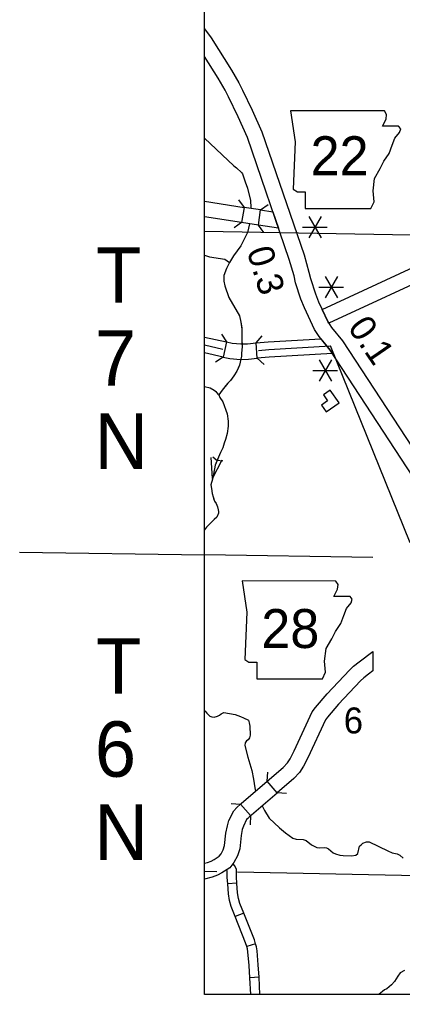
# Model space of a CAD drawing. Extents: x 1374139 to 1377472, y 1168351 to 1170484.
# Drawn here: x 1375030 to 1375154.2, y 1168653.8 to 1168970.5 of the extents above; entities that cross this region are included whole.
import ezdxf

# ---------------------------------------------------------------- set-up
doc = ezdxf.new("R2010")
doc.units = 0
for name, color, linetype in [('14', 7, 'Continuous'), ('26', 7, 'Continuous'), ('Default', 7, 'Continuous')]:
    doc.layers.add(name, color=color, linetype=linetype)

msp = doc.modelspace()

# ---------------------------------------------------------------- linework, layer by layer
at = {"layer": '14'}
msp.add_line((1375030.01, 1168797.49), (1375090, 1168796.6), dxfattribs=at)
at = {"layer": '26'}
msp.add_lwpolyline([(1375090, 1169579.43), (1376597.43, 1169579.43), (1376597.43, 1168653.79), (1375090, 1168653.79)], close=True, dxfattribs=at)
at = {"layer": 'Default'}
for p, q in [((1375090, 1168958.55), (1375090, 1168967.47)), ((1375090, 1168967.47), (1375092.12, 1168964.57)), ((1375092.12, 1168964.57), (1375098.76, 1168954.03)), ((1375094.49, 1168951.44), (1375090, 1168958.55)), ((1375098.76, 1168954.03), (1375101.14, 1168949.96)), ((1375096.74, 1168947.58), (1375094.49, 1168951.44)), ((1375101.14, 1168949.96), (1375102.31, 1168947.59)), ((1375097.81, 1168945.41), (1375096.74, 1168947.58)), ((1375102.31, 1168947.59), (1375105.45, 1168941.02)), ((1375100.91, 1168938.92), (1375097.81, 1168945.41)), ((1375105.45, 1168941.02), (1375108.6, 1168933.98)), ((1375103.94, 1168932.14), (1375100.91, 1168938.92)), ((1375108.6, 1168933.98), (1375122.29, 1168894.07)), ((1375117.52, 1168892.58), (1375103.94, 1168932.14)), ((1375090, 1168906.41), (1375090, 1168911.46)), ((1375090, 1168911.46), (1375102.84, 1168909.49)), ((1375102.84, 1168909.49), (1375102.03, 1168904.56)), ((1375107.48, 1168903.72), (1375108.21, 1168908.67)), ((1375102.03, 1168904.56), (1375090, 1168906.41)), ((1375112.21, 1168908.06), (1375114.04, 1168902.72)), ((1375127.82, 1168906.54), (1375123.82, 1168899.61)), ((1375123.82, 1168906.54), (1375127.82, 1168899.61)), ((1375121.82, 1168903.07), (1375129.82, 1168903.07)), ((1375122.29, 1168894.07), (1375123.89, 1168888.44)), ((1375119.04, 1168887.2), (1375117.52, 1168892.58)), ((1375119.55, 1168885), (1375119.04, 1168887.2)), ((1375123.89, 1168888.44), (1375124.37, 1168886.33)), ((1375133.12, 1168887), (1375129.12, 1168880.07)), ((1375129.12, 1168887), (1375133.12, 1168880.07)), ((1375121.27, 1168879.68), (1375119.55, 1168885)), ((1375124.37, 1168886.33), (1375125.96, 1168881.41)), ((1375127.12, 1168883.54), (1375135.12, 1168883.54)), ((1375125.96, 1168881.41), (1375127.03, 1168878.85)), ((1375122.44, 1168876.85), (1375121.27, 1168879.68)), ((1375127.03, 1168878.85), (1375130.07, 1168872.21)), ((1375125.69, 1168869.78), (1375122.44, 1168876.85)), ((1375130.07, 1168872.21), (1375131.19, 1168870.5)), ((1375127.15, 1168867.54), (1375125.69, 1168869.78)), ((1375130.76, 1168863.14), (1375127.15, 1168867.54)), ((1375131.19, 1168870.5), (1375134.8, 1168866.1)), ((1375090, 1168862.23), (1375090, 1168867.35)), ((1375090, 1168867.35), (1375097.14, 1168865.77)), ((1375097.14, 1168865.77), (1375096.09, 1168860.88)), ((1375107.08, 1168860.46), (1375106.73, 1168865.45)), ((1375134.8, 1168866.1), (1375177.57, 1168800.51)), ((1375096.09, 1168860.88), (1375090, 1168862.23)), ((1375171.6, 1168800.51), (1375130.76, 1168863.14)), ((1375131.17, 1168859.93), (1375127.17, 1168853)), ((1375127.17, 1168859.93), (1375131.17, 1168853)), ((1375125.17, 1168856.47), (1375133.17, 1168856.47)), ((1375092.59, 1168821.36), (1375092.22, 1168828.21)), ((1375092.59, 1168821.36), (1375095.7, 1168827.48)), ((1375092.69, 1168828.41), (1375094.14, 1168827.3)), ((1375095.97, 1168827.06), (1375094.16, 1168827.29)), ((1375140.13, 1168761.84), (1375144.64, 1168765.16)), ((1375144.64, 1168765.16), (1375144.64, 1168758.95)), ((1375137.05, 1168759.17), (1375138.38, 1168760.41)), ((1375138.38, 1168760.41), (1375140.13, 1168761.84)), ((1375129.79, 1168751.42), (1375137.05, 1168759.17)), ((1375141.68, 1168756.65), (1375140.59, 1168755.63)), ((1375143.19, 1168757.89), (1375141.68, 1168756.65)), ((1375144.64, 1168758.95), (1375143.19, 1168757.89)), ((1375140.59, 1168755.63), (1375133.5, 1168748.07)), ((1375125.99, 1168747.04), (1375129.79, 1168751.42)), ((1375124.91, 1168745.57), (1375125.99, 1168747.04)), ((1375133.5, 1168748.07), (1375129.9, 1168743.92)), ((1375119.06, 1168732.9), (1375124.91, 1168745.57)), ((1375129.9, 1168743.92), (1375129.24, 1168743.02)), ((1375129.24, 1168743.02), (1375123.56, 1168730.72)), ((1375117.8, 1168730.39), (1375119.06, 1168732.9)), ((1375115.57, 1168727.58), (1375116.91, 1168729)), ((1375116.91, 1168729), (1375117.8, 1168730.39)), ((1375123.56, 1168730.72), (1375122.15, 1168727.92)), ((1375110.31, 1168723.07), (1375115.57, 1168727.58)), ((1375120.87, 1168725.92), (1375119.03, 1168723.96)), ((1375122.15, 1168727.92), (1375120.87, 1168725.92)), ((1375113.61, 1168719.31), (1375110.31, 1168723.07)), ((1375119.03, 1168723.96), (1375113.61, 1168719.31)), ((1375100.45, 1168714.51), (1375101.66, 1168715.63)), ((1375101.66, 1168715.63), (1375104.98, 1168711.89)), ((1375097.95, 1168710.35), (1375099.47, 1168713.4)), ((1375099.47, 1168713.4), (1375100.45, 1168714.51)), ((1375097.43, 1168708.63), (1375097.95, 1168710.35)), ((1375103.66, 1168710.59), (1375102.62, 1168708.49)), ((1375104.03, 1168711.01), (1375103.66, 1168710.59)), ((1375104.98, 1168711.89), (1375104.03, 1168711.01)), ((1375096.54, 1168702.15), (1375096.92, 1168706.21)), ((1375096.92, 1168706.21), (1375097.43, 1168708.63)), ((1375102.28, 1168707.39), (1375101.88, 1168705.46)), ((1375102.62, 1168708.49), (1375102.28, 1168707.39)), ((1375101.88, 1168705.46), (1375101.47, 1168701.12)), ((1375095.37, 1168699.46), (1375096.09, 1168700.78)), ((1375096.09, 1168700.78), (1375096.54, 1168702.15)), ((1375101.47, 1168701.12), (1375100.7, 1168698.79)), ((1375090, 1168696.41), (1375091, 1168696.65)), ((1375090, 1168691.28), (1375090, 1168696.41)), ((1375091, 1168696.65), (1375092.14, 1168697.08)), ((1375092.14, 1168697.08), (1375093.11, 1168697.6)), ((1375093.11, 1168697.6), (1375094.77, 1168698.69)), ((1375094.77, 1168698.69), (1375095.37, 1168699.46)), ((1375099.56, 1168696.69), (1375098.19, 1168694.96)), ((1375100.7, 1168698.79), (1375099.56, 1168696.69)), ((1375095.68, 1168693.3), (1375094.22, 1168692.52)), ((1375098.19, 1168694.96), (1375095.68, 1168693.3)), ((1375092.46, 1168691.85), (1375090, 1168691.28)), ((1375094.22, 1168692.52), (1375092.46, 1168691.85)), ((1375100.54, 1168689.99), (1375097.55, 1168689.79)), ((1375102.75, 1168680.22), (1375099.96, 1168679.11)), ((1375106.59, 1168670.24), (1375103.71, 1168669.39)), ((1375107.69, 1168659.42), (1375104.69, 1168659.25))]:
    msp.add_line(p, q, dxfattribs=at)
for points in [[(1375117.94, 1168940.9), (1375119.46, 1168930.75), (1375118.78, 1168915.35), (1375120.14, 1168914.51), (1375122.68, 1168914.51), (1375122.68, 1168909.09), (1375143.99, 1168909.09), (1375145.01, 1168911.29), (1375144.67, 1168914.84), (1375145.18, 1168918.9), (1375147.04, 1168922.12), (1375148.22, 1168924.49), (1375149.91, 1168927.03), (1375150.93, 1168929.73), (1375151.77, 1168931.93), (1375153.3, 1168933.79), (1375153.64, 1168934.98), (1375152.96, 1168935.82), (1375147.71, 1168935.82), (1375148.9, 1168938.19), (1375149.07, 1168939.71), (1375148.37, 1168940.88)], [(1375133.67, 1168845.97), (1375130.76, 1168850.14), (1375128.56, 1168848.6), (1375129.94, 1168846.63), (1375127.97, 1168845.26), (1375129.5, 1168843.06)], [(1375102.23, 1168788.13), (1375103.75, 1168777.98), (1375103.07, 1168762.58), (1375104.42, 1168761.74), (1375106.96, 1168761.74), (1375106.96, 1168756.32), (1375128.28, 1168756.32), (1375129.29, 1168758.52), (1375128.96, 1168762.08), (1375129.46, 1168766.14), (1375131.32, 1168769.35), (1375132.51, 1168771.72), (1375134.2, 1168774.26), (1375135.22, 1168776.96), (1375136.06, 1168779.16), (1375137.58, 1168781.02), (1375137.92, 1168782.21), (1375137.25, 1168783.05), (1375132, 1168783.05), (1375133.19, 1168785.42), (1375133.35, 1168786.95), (1375132.65, 1168788.11)]]:
    msp.add_lwpolyline(points, close=True, dxfattribs=at)
for points in [[(1375090, 1168931.98), (1375099.51, 1168922.99), (1375100.34, 1168922.38), (1375102.01, 1168920.85), (1375102.31, 1168920.39), (1375103.21, 1168917.81)], [(1375103.21, 1168917.81), (1375103.92, 1168915.71), (1375104.91, 1168911.67), (1375105.07, 1168909.41), (1375105.07, 1168909.2)], [(1375101.08, 1168911.93), (1375102.84, 1168909.49)], [(1375108.21, 1168908.67), (1375102.84, 1168909.49)], [(1375108.21, 1168908.67), (1375110.61, 1168910.46)], [(1375108.21, 1168908.67), (1375112.21, 1168908.06)], [(1375104.6, 1168904.13), (1375103.97, 1168901.32), (1375101.76, 1168897.04), (1375099.37, 1168893.76), (1375098.17, 1168891.63), (1375097.16, 1168889.65), (1375096.26, 1168887.34), (1375096.29, 1168885.54), (1375096.6, 1168884.04), (1375097.93, 1168880.2), (1375101.33, 1168874.28)], [(1375102.03, 1168904.56), (1375099.59, 1168902.81)], [(1375107.48, 1168903.72), (1375102.03, 1168904.56)], [(1375109.27, 1168901.32), (1375107.48, 1168903.72)], [(1375114.04, 1168902.72), (1375107.48, 1168903.72)], [(1375193.67, 1168899.77), (1375090, 1168901.68)], [(1375090, 1168893.91), (1375091.6, 1168893.38), (1375096.64, 1168892.64), (1375098.17, 1168891.63)], [(1375128.18, 1168876.34), (1375166.71, 1168894.16)], [(1375168.77, 1168889.6), (1375130.32, 1168871.83)], [(1375101.33, 1168874.28), (1375101.82, 1168872.15), (1375102.16, 1168869.89), (1375102.09, 1168868.17), (1375102.13, 1168865.99), (1375102.22, 1168864.32), (1375101.98, 1168862), (1375101.99, 1168861.2), (1375101.41, 1168858.25), (1375100.52, 1168856.24), (1375099.54, 1168854.73), (1375098.45, 1168853.3), (1375097.6, 1168852.41), (1375095.69, 1168850.13), (1375094.61, 1168848.64), (1375095.03, 1168847.68), (1375095.94, 1168846.28), (1375097.33, 1168842.45), (1375097.67, 1168839.99), (1375097.66, 1168838.46), (1375097.4, 1168836.08), (1375096.77, 1168834.07), (1375096.4, 1168832.94), (1375095.93, 1168831.4), (1375095.24, 1168829.91), (1375094.91, 1168829.15), (1375093.52, 1168825.75), (1375092.9, 1168822.82), (1375092.61, 1168821.19), (1375092.05, 1168819.37), (1375092.29, 1168818.15), (1375092.47, 1168816.58), (1375092.79, 1168815.46), (1375093.26, 1168814.05), (1375093.75, 1168813.25), (1375094.2, 1168812.17), (1375094.53, 1168810.71), (1375094.53, 1168810.17), (1375094.02, 1168808.9), (1375093.15, 1168808.05), (1375091.84, 1168806.76), (1375090.69, 1168805.65), (1375090.02, 1168804.77), (1375090, 1168804.73)], [(1375101.33, 1168874.28), (1375101.82, 1168872.15), (1375102.09, 1168870.39)], [(1375130.32, 1168871.83), (1375130.07, 1168872.21), (1375128.18, 1168876.34)], [(1375095.52, 1168868.29), (1375097.14, 1168865.77)], [(1375102.1, 1168867.76), (1375102.13, 1168865.99), (1375102.18, 1168865.17)], [(1375106.73, 1168865.45), (1375108.7, 1168867.71)], [(1375090, 1168864.79), (1375095.98, 1168863.47)], [(1375097.14, 1168865.77), (1375099.03, 1168865.35), (1375101.8, 1168865.12), (1375103.92, 1168865.21), (1375106.73, 1168865.45)], [(1375106.73, 1168865.45), (1375110.66, 1168865.78), (1375127.75, 1168866.82)], [(1375107.5, 1168863), (1375110.84, 1168863.28), (1375130.93, 1168864.51)], [(1375127.75, 1168866.82), (1375130.76, 1168863.14), (1375131.48, 1168862.04)], [(1375156.67, 1168800.51), (1375130.93, 1168864.51)], [(1375131.48, 1168862.04), (1375111.02, 1168860.79), (1375107.08, 1168860.46)], [(1375096.09, 1168860.88), (1375093.57, 1168859.25)], [(1375096.09, 1168860.88), (1375098.28, 1168860.4), (1375101.69, 1168860.11), (1375104.23, 1168860.22), (1375107.08, 1168860.46)], [(1375109.35, 1168858.49), (1375107.08, 1168860.46)], [(1375101.01, 1168857.35), (1375100.52, 1168856.24), (1375099.54, 1168854.73), (1375098.45, 1168853.3), (1375097.6, 1168852.41), (1375096.4, 1168850.97)], [(1375094.61, 1168848.64), (1375093.88, 1168849.48), (1375093.18, 1168849.99), (1375091.86, 1168850.74), (1375090, 1168851.15)], [(1375094.79, 1168848.89), (1375094.61, 1168848.64), (1375095.03, 1168847.68), (1375095.94, 1168846.28), (1375097.33, 1168842.45), (1375097.44, 1168841.63)], [(1375097.66, 1168839.01), (1375097.66, 1168838.46), (1375097.4, 1168836.08), (1375096.77, 1168834.07), (1375096.4, 1168832.94), (1375095.93, 1168831.4), (1375095.9, 1168831.33)], [(1375094.82, 1168828.93), (1375093.52, 1168825.75), (1375092.9, 1168822.82), (1375092.64, 1168821.35)], [(1375092.16, 1168818.81), (1375092.29, 1168818.15), (1375092.47, 1168816.58), (1375092.79, 1168815.46), (1375092.96, 1168814.95)], [(1375092.96, 1168814.95), (1375093.26, 1168814.05), (1375093.75, 1168813.25), (1375094.2, 1168812.17), (1375094.4, 1168811.28)], [(1375093.92, 1168808.8), (1375093.15, 1168808.05), (1375091.84, 1168806.76), (1375090.69, 1168805.65), (1375090.02, 1168804.77), (1375090, 1168804.73)], [(1375144.64, 1168795.79), (1375090, 1168796.6)], [(1375090, 1168746.09), (1375090.23, 1168745.78), (1375090.73, 1168745.2), (1375091.42, 1168744.5), (1375091.76, 1168744.24), (1375092.38, 1168743.95), (1375093.1, 1168743.83), (1375094.22, 1168744.2), (1375094.89, 1168744.57), (1375095.39, 1168744.95), (1375096.27, 1168745.36), (1375098.16, 1168745.11), (1375099.95, 1168744.72), (1375101.69, 1168744.11), (1375102.65, 1168743.64)], [(1375090, 1168746.09), (1375090.23, 1168745.78), (1375090.73, 1168745.2), (1375091.42, 1168744.5), (1375091.76, 1168744.24), (1375092.38, 1168743.95), (1375093.1, 1168743.83), (1375093.91, 1168744.1)], [(1375096.23, 1168745.34), (1375096.27, 1168745.36), (1375098.16, 1168745.11), (1375099.95, 1168744.72), (1375101.69, 1168744.11), (1375102.65, 1168743.64)], [(1375102.65, 1168743.64), (1375104.23, 1168742.87), (1375104.52, 1168742.07), (1375104.75, 1168740.97), (1375104.81, 1168738), (1375104.61, 1168737.22), (1375104.16, 1168736.54), (1375103.66, 1168736.17), (1375103.25, 1168735.55), (1375103.08, 1168734.69), (1375104.06, 1168730.89), (1375105.39, 1168726.53), (1375105.91, 1168723.79), (1375106.33, 1168720.88), (1375106.59, 1168719.89)], [(1375110.31, 1168723.07), (1375110.51, 1168726.06)], [(1375101.66, 1168715.63), (1375101.88, 1168715.84), (1375110.31, 1168723.07)], [(1375104.98, 1168711.89), (1375105.21, 1168712.1), (1375113.61, 1168719.31)], [(1375116.6, 1168719.11), (1375113.61, 1168719.31)], [(1375098.66, 1168715.8), (1375101.66, 1168715.63)], [(1375108.69, 1168715.03), (1375109.46, 1168713.55), (1375111, 1168711.1), (1375114.38, 1168707.9), (1375116.23, 1168706.31), (1375118.66, 1168704.6), (1375119.7, 1168704.23), (1375122, 1168704.16), (1375122.98, 1168703.83), (1375124.76, 1168702.42), (1375126.47, 1168701.51), (1375127.39, 1168701.44), (1375129.03, 1168701.49), (1375129.63, 1168701.39), (1375130.23, 1168701.12), (1375131.75, 1168699.84), (1375132.5, 1168699.45), (1375133.86, 1168699.04), (1375134.94, 1168698.9), (1375137.69, 1168698.88), (1375139.15, 1168699.05), (1375139.73, 1168699.54), (1375140.33, 1168701.93), (1375140.82, 1168702.45), (1375141.4, 1168702.96), (1375142.61, 1168703.43), (1375143.43, 1168703.39), (1375149.43, 1168700.41), (1375150.87, 1168699.86), (1375152.53, 1168699.47), (1375153.35, 1168699.01), (1375154.42, 1168698.12)], [(1375104.98, 1168711.89), (1375104.81, 1168708.9)], [(1375090, 1168693.85), (1375094.05, 1168693.77)], [(1375097.55, 1168689.79), (1375097.41, 1168691.81), (1375097.41, 1168693.73), (1375097.31, 1168693.96), (1375097.07, 1168694.22)], [(1375100.54, 1168689.99), (1375100.41, 1168691.91), (1375100.41, 1168694.38), (1375099.85, 1168695.61), (1375099.25, 1168696.29)], [(1375100.74, 1168693.63), (1375191.1, 1168691.79), (1375251.59, 1168691.75)], [(1375099.96, 1168679.11), (1375098.65, 1168682.4), (1375098.11, 1168684.37), (1375097.77, 1168686.5), (1375097.55, 1168689.79)], [(1375102.75, 1168680.22), (1375101.5, 1168683.36), (1375101.05, 1168685), (1375100.76, 1168686.84), (1375100.54, 1168689.99)], [(1375103.71, 1168669.39), (1375103.36, 1168670.6), (1375099.96, 1168679.11)], [(1375106.59, 1168670.24), (1375106.19, 1168671.58), (1375102.75, 1168680.22)], [(1375104.69, 1168659.25), (1375104.47, 1168663.21), (1375104.11, 1168667.65), (1375103.95, 1168668.59), (1375103.71, 1168669.39)], [(1375107.69, 1168659.42), (1375107.47, 1168663.41), (1375107.09, 1168668.02), (1375106.87, 1168669.27), (1375106.59, 1168670.24)], [(1375154.85, 1168661.6), (1375153.47, 1168660.78), (1375152.7, 1168659.74), (1375151.62, 1168657.99), (1375150.69, 1168656.94)], [(1375105, 1168653.79), (1375104.69, 1168659.25)], [(1375108.01, 1168653.79), (1375107.69, 1168659.42)], [(1375150.69, 1168656.94), (1375149.2, 1168655.68), (1375148.44, 1168655.26), (1375146.61, 1168653.79)]]:
    msp.add_lwpolyline(points, dxfattribs=at)

# ---------------------------------------------------------------- texts
for s, height, p in [('22', 12.66, (1375124.41, 1168919.93)), ('T', 18, (1375054.84, 1168878.53)), ('7', 18, (1375054.46, 1168851.53)), ('N', 18, (1375054.34, 1168824.53)), ('28', 12.66, (1375108.42, 1168766.34)), ('T', 18, (1375054.78, 1168751.53)), ('6', 8.44, (1375135.17, 1168738.59)), ('6', 18, (1375054.44, 1168724.53)), ('N', 18, (1375054.28, 1168697.53))]:
    msp.add_text(s, height=height, dxfattribs=at).set_placement(p)
for s, rotation, p in [('0.3', 286.8044, (1375103.65, 1168895.41)), ('0.1', 304.4605, (1375136.23, 1168870.5))]:
    msp.add_text(s, height=8.448, rotation=rotation, dxfattribs=at).set_placement(p)

doc.saveas('drawing.dxf')
